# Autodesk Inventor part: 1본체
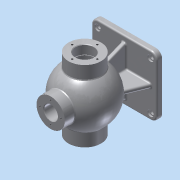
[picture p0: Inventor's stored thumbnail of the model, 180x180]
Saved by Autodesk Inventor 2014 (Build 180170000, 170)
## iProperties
Created: 2017-01
Part Number: 1본체
Material: Aluminum 6061
Document SubType Name: Modeling
Designer: ksu
Density: 2.71 g/cm^3
Appearance: Aluminum - Flat
Author: ksu
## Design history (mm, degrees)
sketch "Sketch1"
  geometry: L1 (-62.5, 57.5)-(62.5, 57.5); L2 (62.5, 57.5)-(62.5, -57.5); L3 (62.5, -57.5)-(-62.5, -57.5); L4 (-62.5, -57.5)-(-62.5, 57.5); L5 (-62.5, 57.5)-(62.5, -57.5); L6 (62.5, 57.5)-(-62.5, -57.5); 1 further point
  constraints: 12 end point, 2 midpoint, 2 parallel, 1 horizontal, 1 perpendicular
  dimensions: "d0" = 125 distance of L2.end L3.end; "d1" = 115 distance of L1.end L2.end
extrude "Extrusion1" new body sketch "Sketch1" distance "d2" = 10; taper "d3" = 0 deg
sketch "Sketch3"
  geometry: L1 (0, 0)-(0, 85); L2 (51.884, 95.82)-(-51.884, 74.18); A1 r 53 centre (0, 85) between (51.884, 95.82) and (-51.884, 74.18)
  constraints: 4 end point, 2 point on circle, 1 centre point, 1 coincident, 1 midpoint, 1 vertical
  dimensions: "d6" = 85 distance of L1.start L1.end; "d7" = 106 diameter of A1
revolve "Revolution1" sketch "Sketch3" stored, may be unused: angle "d8" = 90 deg
sketch "Sketch4"
  geometry: L1 (62.5, 0)-(-62.5, 0) reference; L2 (-62.5, 10)-(62.5, 10) reference; L3 (-62.5, 0)-(-62.5, 10) reference; L4 (-52.5, 10)-(-31.054, 63.082); L5 (52.5, 10)-(31.054, 63.082); L6 (-31.054, 63.082)-(31.054, 63.082); L7 (-52.5, 10)-(52.5, 10); 1 further point
  constraints: 8 end point, 1 collinear, 1 point on line
  dimensions: "d9" = 22 deg angle of L4 L3; "d10" = 10 distance from line of L3 L4.start
extrude "Extrusion2" join sketch "Sketch4" stored distance "d11" = 8; taper "d12" = 0 deg
sketch "Sketch5"
  geometry: L1 (57.5, 0)-(-57.5, 0) reference; L2 (-57.5, 10)-(57.5, 10) reference; L3 (-57.5, 0)-(-57.5, 10) reference; L4 (-47.5, 10)-(-22.261, 72.468); L5 (47.5, 10)-(22.261, 72.468); L6 (-22.261, 72.468)-(22.261, 72.468); L7 (-47.5, 10)-(47.5, 10); 1 further point
  constraints: 8 end point, 1 collinear, 1 point on line
  dimensions: "d13" = 22 deg angle of L4 L3; "d14" = 10 distance from line of L4.start L3
extrude "Extrusion3" join sketch "Sketch5" stored distance "d15" = 8; taper "d16" = 0 deg
workplane "Work Plane1"
sketch "Sketch6"
  geometry: L1 (62.5, 0)-(-62.5, 0) reference; C1 r 31 at (0, 85); 1 further point
  constraints: 1 centre point
  dimensions: "d19" = 62 diameter of C1
extrude "Extrusion4" join sketch "Sketch6" distance "d20" = 136; taper "d21" = 0 deg
workplane "Work Plane2"
sketch "Sketch7"
  geometry: C1 r 27 at (0, 0); 1 further point
  constraints: 1 centre point, 1 coincident
  dimensions: "d23" = 54 diameter of C1
extrude "Extrusion5" join sketch "Sketch7" distance "d24" = 50; taper "d25" = 0 deg
fillet "Fillet1" dims "d26" = 12
sketch "Sketch8"
  geometry: L1 (62.5, -45.5)-(62.5, 45.5) reference; L2 (50.5, 57.5)-(-50.5, 57.5) reference; L3 (-62.5, 45.5)-(-62.5, -45.5) reference; 5 further points
  dimensions: "d27" = 12 distance from line of L3 point (-50.5, 45.5); "d28" = 12 distance from line of L1 point (50.5, 45.5); "d29" = 12 distance from line of L1 point (50.5, -45.5); "d30" = 12 distance from line of L3 point (-50.5, -45.5); "d31" = 12 distance from line of L2 point (-50.5, 45.5); "d32" = 12 distance from line of L2 point (50.5, 45.5); "d33" = 91 distance of point (50.5, -45.5) point (50.5, 45.5); "d34" = 91 distance of point (-50.5, -45.5) point (-50.5, 45.5)
hole "Hole1" sketch "Sketch8" at (-50.5, 45.5), (50.5, 45.5), (50.5, -45.5), (-50.5, -45.5) diameter "d35" = 8; stored, may be unused: countersink angle "d39" = 90 deg, drill point angle "d41" = 118 deg; dims "d36" = 6, "d37" = 12, "d38" = 3, "d40" = 8
sketch "Sketch9"
  geometry: L1 (-68, 116)-(-68, 54) reference; L2 (68, 116)-(68, 54) reference; L3 (-68, 85)-(68, 85); L4 (-68, 85)-(-18.895, 85); L5 (-18.895, 85)-(-18.895, 102.5); L6 (-39.278, 102.5)-(-68, 102.5); L7 (-68, 102.5)-(-68, 85); L8 (68, 85)-(52, 85); L9 (52, 85)-(52, 102.5); L10 (52, 102.5)-(68, 102.5); L11 (68, 102.5)-(68, 85); L12 (52, 85)-(50.25, 85); L13 (50.25, 85)-(50.25, 103.5); L14 (50.25, 103.5)-(52, 103.5); L15 (52, 103.5)-(52, 85); L16 (50.25, 85)-(28.753, 85); L17 (28.753, 85)-(28.753, 102.5); L18 (28.753, 102.5)-(50.25, 102.5); L19 (50.25, 102.5)-(50.25, 85); A1 r 43 centre (0, 85) between (43, 85) and (-43, 85); 1 further point
  constraints: 34 end point, 8 parallel, 4 horizontal, 4 perpendicular, 3 midpoint, 3 point on circle, 2 point on line, 1 centre point
  dimensions: "d42" = 86 diameter of A1; "d43" = 17.5 distance of L5.end L4.end; "d44" = 16 distance of L9.end L10.end; "d45" = 17.5 distance of L8.end L9.end; "d46" = 1.75 distance of L13.end L14.end; "d47" = 18.5 distance of L12.end L13.end; "d48" = 17.5 distance of L16.end L17.end
revolve "Revolution2" sketch "Sketch9" stored, may be unused: angle "d49" = 90 deg
sketch "Sketch10"
  geometry: C1 r 27 at (0, 0) reference; C2 r 13 at (0, 0)
  constraints: 1 centre point, 1 coincident
  dimensions: "d50" = 26 diameter of C2
extrude "Extrusion6" cut sketch "Sketch10" distance "d51" = 50; taper "d52" = 0 deg
sketch "Sketch11"
  geometry: C1 r 31 at (0, 0) reference; A1 r 24 centre (0, 0) between (0, 24) and (24, 0); 3 further points
  constraints: 4 point on circle, 1 centre point, 1 coincident
  dimensions: "d54" = 48 diameter of A1
hole "Hole2" sketch "Sketch11" at (0, 24), (24, 0), (0, -24), (-24, 0) diameter "d55" = 3.459; stored, may be unused: countersink angle "d59" = 90 deg, drill point angle "d61" = 118 deg; dims "d56" = 16, "d57" = 4, "d58" = 2, "d60" = 19
sketch "Sketch12"
  geometry: C1 r 31 at (0, 0) reference; A1 r 22.5 centre (0, 0) between (0, 22.5) and (-22.5, 0); 3 further points
  constraints: 4 point on circle, 1 centre point, 1 coincident
  dimensions: "d62" = 45 diameter of A1
hole "Hole3" sketch "Sketch12" at (0, 22.5), (-22.5, 0), (0, -22.5), (22.5, 0) diameter "d63" = 3.459; stored, may be unused: countersink angle "d67" = 90 deg, drill point angle "d69" = 118 deg; dims "d64" = 12, "d65" = 4, "d66" = 2, "d68" = 15
workplane "Work Plane3"
sketch "Sketch13"
  geometry: L1 (-20.739, 143.002)-(20.739, 143.002); L2 (20.739, 143.002)-(20.739, 136.998); L3 (20.739, 136.998)-(-20.739, 136.998); L4 (-20.739, 136.998)-(-20.739, 143.002); L5 (27, 150)-(-27, 150) reference; L6 (27, 150)-(27, 130.607) reference; L7 (27, 140)-(0, 140); 1 further point
  constraints: 2 end point, 1 perpendicular, 1 point on line, 2 other
  dimensions: "d71" = 27 distance of L7.start L7.end; "d72" = 10 distance between parallel lines of L7 L5
emboss "Emboss1" sketch "Sketch13" dims "d0" = 125, "d1" = 115, "d9" = 22 deg, "d10" = 10, "d73" = 0.5, "d74" = 0
sketch "Sketch14"
  geometry: C1 r 27 at (0, 0) reference; A1 r 20 centre (0, 0) between (0, 20) and (-20, 0); 2 further points
  constraints: 4 point on circle, 1 centre point, 1 coincident
  dimensions: "d75" = 40 diameter of A1
hole "Hole4" sketch "Sketch14" at (0, 20), (-20, 0), (0, -20), (20, 0) diameter "d76" = 3.459; stored, may be unused: countersink angle "d80" = 90 deg, drill point angle "d82" = 118 deg; dims "d77" = 9, "d78" = 4, "d79" = 2, "d81" = 11
fillet "Fillet2" dims "d83" = 3
fillet "Fillet3" dims "d84" = 3
chamfer "Chamfer1" distance "d85" = 1; stored, may be unused: second distance "d86" = 2, angle "d87" = 45 deg
chamfer "Chamfer2" distance "d88" = 1; stored, may be unused: second distance "d89" = 2, angle "d90" = 45 deg
body "Solid1"
other parameters: "d17" = 68, "d70" = -27
